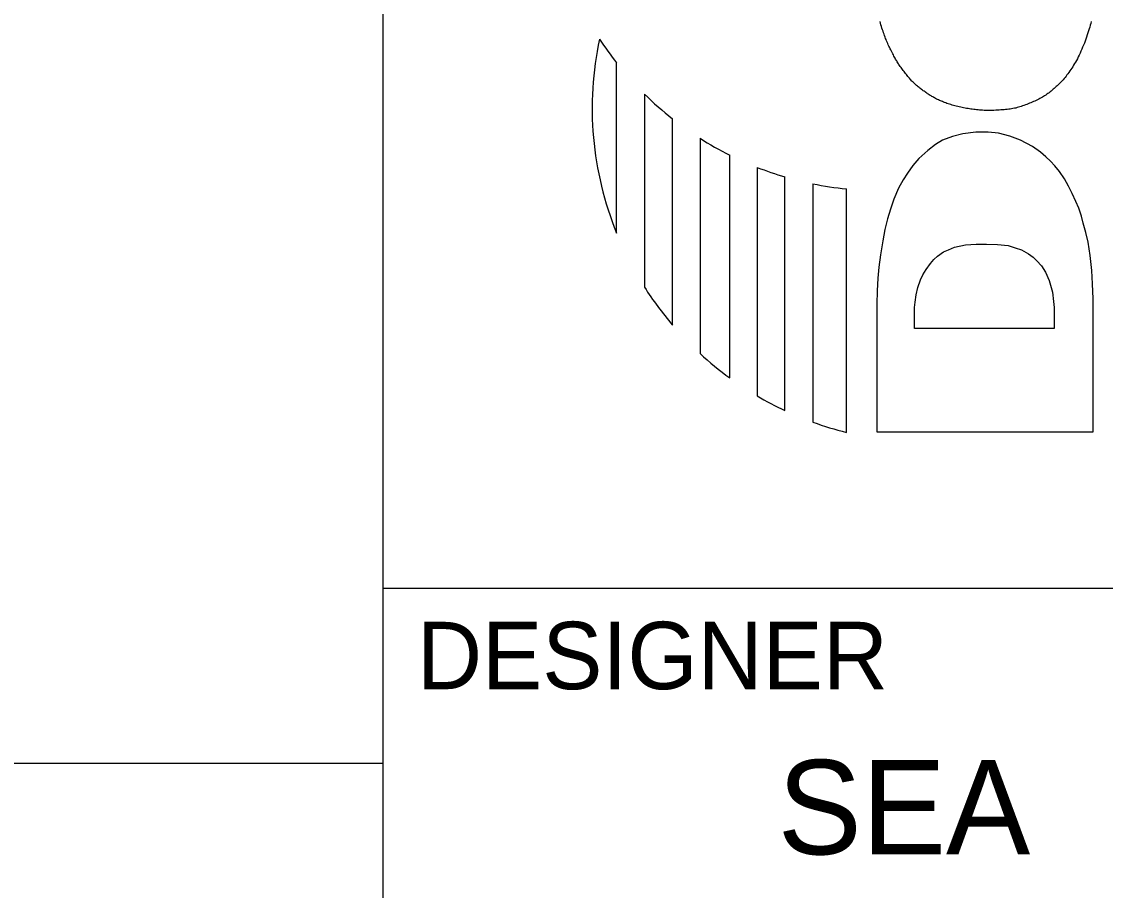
# Model space of a CAD drawing. Extents: x -1 to 34, y 0 to 22.
# Drawn here: x 31.464 to 33.071, y 2.552 to 3.841 of the extents above; entities that cross this region are included whole.
import ezdxf

# ---------------------------------------------------------------- set-up
doc = ezdxf.new("R2010")
doc.units = 0
for name, color, linetype in [('CM_Corridor_Final', 7, 'Continuous'), ('MD_P_GRADE_BREAK', 7, 'Continuous'), ('PF_X_Ground_Line', 7, 'Continuous')]:
    doc.layers.add(name, color=color, linetype=linetype)

msp = doc.modelspace()

# ---------------------------------------------------------------- linework, layer by layer
at = {"layer": 'CM_Corridor_Final'}
for p, q in [((32.7374, 3.8383), (32.7368, 3.8409)), ((32.7381, 3.8358), (32.7374, 3.8383)), ((32.7388, 3.8334), (32.7381, 3.8358)), ((32.7396, 3.831), (32.7388, 3.8334)), ((32.7403, 3.8286), (32.7396, 3.831)), ((32.7411, 3.8263), (32.7403, 3.8286)), ((32.7418, 3.8241), (32.7411, 3.8263)), ((33.046, 3.8269), (33.0451, 3.8239)), ((33.0469, 3.8298), (33.046, 3.8269)), ((33.0477, 3.8326), (33.0469, 3.8298)), ((33.0484, 3.8353), (33.0477, 3.8326)), ((33.0491, 3.838), (33.0484, 3.8353)), ((33.0498, 3.8406), (33.0491, 3.838)), ((32.7426, 3.8219), (32.7418, 3.8241)), ((32.7434, 3.8198), (32.7426, 3.8219)), ((32.7441, 3.8178), (32.7434, 3.8198)), ((32.7449, 3.8158), (32.7441, 3.8178)), ((32.7457, 3.8139), (32.7449, 3.8158)), ((32.7465, 3.812), (32.7457, 3.8139)), ((32.7473, 3.8101), (32.7465, 3.812)), ((32.7482, 3.8082), (32.7473, 3.8101)), ((33.0409, 3.8117), (33.0397, 3.8086)), ((33.042, 3.8148), (33.0409, 3.8117)), ((33.0431, 3.8178), (33.042, 3.8148)), ((33.0441, 3.8209), (33.0431, 3.8178)), ((33.0451, 3.8239), (33.0441, 3.8209)), ((32.749, 3.8063), (32.7482, 3.8082)), ((32.7499, 3.8044), (32.749, 3.8063)), ((32.7508, 3.8025), (32.7499, 3.8044)), ((32.7518, 3.8005), (32.7508, 3.8025)), ((32.7527, 3.7986), (32.7518, 3.8005)), ((32.7537, 3.7967), (32.7527, 3.7986)), ((32.7546, 3.7948), (32.7537, 3.7967)), ((32.7555, 3.7929), (32.7546, 3.7948)), ((32.7565, 3.7912), (32.7555, 3.7929)), ((33.0333, 3.7938), (33.032, 3.791)), ((33.0346, 3.7966), (33.0333, 3.7938)), ((33.036, 3.7996), (33.0346, 3.7966)), ((33.0372, 3.8026), (33.036, 3.7996)), ((33.0385, 3.8056), (33.0372, 3.8026)), ((33.0397, 3.8086), (33.0385, 3.8056)), ((32.7573, 3.7895), (32.7565, 3.7912)), ((32.7582, 3.7879), (32.7573, 3.7895)), ((32.759, 3.7864), (32.7582, 3.7879)), ((32.7598, 3.7849), (32.759, 3.7864)), ((32.7606, 3.7836), (32.7598, 3.7849)), ((32.7614, 3.7822), (32.7606, 3.7836)), ((32.7622, 3.7809), (32.7614, 3.7822)), ((32.7631, 3.7795), (32.7622, 3.7809)), ((32.7639, 3.7782), (32.7631, 3.7795)), ((32.7648, 3.7768), (32.7639, 3.7782)), ((32.7658, 3.7754), (32.7648, 3.7768)), ((33.0252, 3.7783), (33.0238, 3.776)), ((33.0265, 3.7806), (33.0252, 3.7783)), ((33.0279, 3.7831), (33.0265, 3.7806)), ((33.0293, 3.7856), (33.0279, 3.7831)), ((33.0306, 3.7882), (33.0293, 3.7856)), ((33.032, 3.791), (33.0306, 3.7882)), ((32.7668, 3.774), (32.7658, 3.7754)), ((32.7678, 3.7726), (32.7668, 3.774)), ((32.7689, 3.7711), (32.7678, 3.7726)), ((32.77, 3.7696), (32.7689, 3.7711)), ((32.7711, 3.7681), (32.77, 3.7696)), ((32.7723, 3.7666), (32.7711, 3.7681)), ((32.7734, 3.7651), (32.7723, 3.7666)), ((32.7746, 3.7636), (32.7734, 3.7651)), ((32.7758, 3.7621), (32.7746, 3.7636)), ((32.777, 3.7607), (32.7758, 3.7621)), ((32.7781, 3.7593), (32.777, 3.7607)), ((33.0139, 3.7615), (33.0125, 3.7596)), ((33.0154, 3.7634), (33.0139, 3.7615)), ((33.0168, 3.7653), (33.0154, 3.7634)), ((33.0182, 3.7674), (33.0168, 3.7653)), ((33.0196, 3.7694), (33.0182, 3.7674)), ((33.021, 3.7716), (33.0196, 3.7694)), ((33.0224, 3.7737), (33.021, 3.7716)), ((33.0238, 3.776), (33.0224, 3.7737)), ((32.7793, 3.7579), (32.7781, 3.7593)), ((32.7804, 3.7566), (32.7793, 3.7579)), ((32.7815, 3.7553), (32.7804, 3.7566)), ((32.7826, 3.7542), (32.7815, 3.7553)), ((32.7836, 3.753), (32.7826, 3.7542)), ((32.7846, 3.752), (32.7836, 3.753)), ((32.7857, 3.751), (32.7846, 3.752)), ((32.7867, 3.75), (32.7857, 3.751)), ((32.7877, 3.749), (32.7867, 3.75)), ((32.7888, 3.748), (32.7877, 3.749)), ((32.7899, 3.747), (32.7888, 3.748)), ((32.791, 3.746), (32.7899, 3.747)), ((32.7921, 3.745), (32.791, 3.746)), ((32.7933, 3.744), (32.7921, 3.745)), ((32.9995, 3.7455), (32.9981, 3.7442)), ((33.001, 3.7469), (32.9995, 3.7455)), ((33.0024, 3.7483), (33.001, 3.7469)), ((33.0039, 3.7498), (33.0024, 3.7483)), ((33.0053, 3.7513), (33.0039, 3.7498)), ((33.0067, 3.7528), (33.0053, 3.7513)), ((33.0082, 3.7544), (33.0067, 3.7528)), ((33.0096, 3.7561), (33.0082, 3.7544)), ((33.0111, 3.7578), (33.0096, 3.7561)), ((33.0125, 3.7596), (33.0111, 3.7578)), ((32.7946, 3.743), (32.7933, 3.744)), ((32.7958, 3.742), (32.7946, 3.743)), ((32.7971, 3.741), (32.7958, 3.742)), ((32.7983, 3.74), (32.7971, 3.741)), ((32.7996, 3.739), (32.7983, 3.74)), ((32.8009, 3.7381), (32.7996, 3.739)), ((32.8021, 3.7372), (32.8009, 3.7381)), ((32.8034, 3.7363), (32.8021, 3.7372)), ((32.8047, 3.7354), (32.8034, 3.7363)), ((32.8059, 3.7345), (32.8047, 3.7354)), ((32.8072, 3.7337), (32.8059, 3.7345)), ((32.8085, 3.7328), (32.8072, 3.7337)), ((32.8098, 3.732), (32.8085, 3.7328)), ((32.8111, 3.7312), (32.8098, 3.732)), ((32.8124, 3.7304), (32.8111, 3.7312)), ((32.8137, 3.7296), (32.8124, 3.7304)), ((32.815, 3.7288), (32.8137, 3.7296)), ((32.8163, 3.728), (32.815, 3.7288)), ((32.9774, 3.7285), (32.9757, 3.7275)), ((32.9791, 3.7295), (32.9774, 3.7285)), ((32.9808, 3.7306), (32.9791, 3.7295)), ((32.9824, 3.7317), (32.9808, 3.7306)), ((32.9841, 3.7328), (32.9824, 3.7317)), ((32.9857, 3.7339), (32.9841, 3.7328)), ((32.9873, 3.7351), (32.9857, 3.7339)), ((32.9889, 3.7363), (32.9873, 3.7351)), ((32.9905, 3.7376), (32.9889, 3.7363)), ((32.992, 3.7389), (32.9905, 3.7376)), ((32.9936, 3.7402), (32.992, 3.7389)), ((32.9951, 3.7415), (32.9936, 3.7402)), ((32.9966, 3.7428), (32.9951, 3.7415)), ((32.9981, 3.7442), (32.9966, 3.7428)), ((32.8177, 3.7273), (32.8163, 3.728)), ((32.8191, 3.7265), (32.8177, 3.7273)), ((32.8204, 3.7258), (32.8191, 3.7265)), ((32.8218, 3.7251), (32.8204, 3.7258)), ((32.8233, 3.7244), (32.8218, 3.7251)), ((32.8247, 3.7238), (32.8233, 3.7244)), ((32.8262, 3.7231), (32.8247, 3.7238)), ((32.8277, 3.7225), (32.8262, 3.7231)), ((32.8293, 3.7219), (32.8277, 3.7225)), ((32.8309, 3.7212), (32.8293, 3.7219)), ((32.8325, 3.7206), (32.8309, 3.7212)), ((32.8342, 3.72), (32.8325, 3.7206)), ((32.836, 3.7193), (32.8342, 3.72)), ((32.8378, 3.7187), (32.836, 3.7193)), ((32.8397, 3.7181), (32.8378, 3.7187)), ((32.8416, 3.7175), (32.8397, 3.7181)), ((32.8436, 3.7168), (32.8416, 3.7175)), ((32.8456, 3.7163), (32.8436, 3.7168)), ((32.8477, 3.7157), (32.8456, 3.7163)), ((32.8498, 3.7151), (32.8477, 3.7157)), ((32.8519, 3.7146), (32.8498, 3.7151)), ((32.8541, 3.7141), (32.8519, 3.7146)), ((32.8563, 3.7136), (32.8541, 3.7141)), ((32.8585, 3.7131), (32.8563, 3.7136)), ((32.8607, 3.7127), (32.8585, 3.7131)), ((32.8629, 3.7123), (32.8607, 3.7127)), ((32.865, 3.7119), (32.8629, 3.7123)), ((32.9379, 3.7124), (32.9359, 3.712)), ((32.9399, 3.713), (32.9379, 3.7124)), ((32.942, 3.7135), (32.9399, 3.713)), ((32.944, 3.7142), (32.942, 3.7135)), ((32.9461, 3.7148), (32.944, 3.7142)), ((32.9481, 3.7155), (32.9461, 3.7148)), ((32.9501, 3.7162), (32.9481, 3.7155)), ((32.9522, 3.717), (32.9501, 3.7162)), ((32.9542, 3.7178), (32.9522, 3.717)), ((32.9563, 3.7186), (32.9542, 3.7178)), ((32.9583, 3.7194), (32.9563, 3.7186)), ((32.9604, 3.7202), (32.9583, 3.7194)), ((32.9624, 3.7211), (32.9604, 3.7202)), ((32.9644, 3.722), (32.9624, 3.7211)), ((32.9664, 3.7228), (32.9644, 3.722)), ((32.9683, 3.7237), (32.9664, 3.7228)), ((32.9702, 3.7247), (32.9683, 3.7237)), ((32.9721, 3.7256), (32.9702, 3.7247)), ((32.9739, 3.7265), (32.9721, 3.7256)), ((32.9757, 3.7275), (32.9739, 3.7265)), ((32.8672, 3.7115), (32.865, 3.7119)), ((32.8693, 3.7111), (32.8672, 3.7115)), ((32.8714, 3.7108), (32.8693, 3.7111)), ((32.8735, 3.7105), (32.8714, 3.7108)), ((32.8756, 3.7102), (32.8735, 3.7105)), ((32.8777, 3.71), (32.8756, 3.7102)), ((32.8798, 3.7097), (32.8777, 3.71)), ((32.882, 3.7095), (32.8798, 3.7097)), ((32.8841, 3.7093), (32.882, 3.7095)), ((32.8864, 3.7092), (32.8841, 3.7093)), ((32.8886, 3.709), (32.8864, 3.7092)), ((32.891, 3.7089), (32.8886, 3.709)), ((32.8933, 3.7088), (32.891, 3.7089)), ((32.8957, 3.7088), (32.8933, 3.7088)), ((32.8981, 3.7088), (32.8957, 3.7088)), ((32.9006, 3.7088), (32.8981, 3.7088)), ((32.9031, 3.7089), (32.9006, 3.7088)), ((32.9057, 3.7089), (32.9031, 3.7089)), ((32.9082, 3.709), (32.9057, 3.7089)), ((32.9108, 3.7092), (32.9082, 3.709)), ((32.9134, 3.7093), (32.9108, 3.7092)), ((32.9159, 3.7095), (32.9134, 3.7093)), ((32.9183, 3.7097), (32.9159, 3.7095)), ((32.9207, 3.7099), (32.9183, 3.7097)), ((32.923, 3.7101), (32.9207, 3.7099)), ((32.9253, 3.7103), (32.923, 3.7101)), ((32.9275, 3.7106), (32.9253, 3.7103)), ((32.9296, 3.7109), (32.9275, 3.7106)), ((32.9317, 3.7112), (32.9296, 3.7109)), ((32.9338, 3.7116), (32.9317, 3.7112)), ((32.9359, 3.712), (32.9338, 3.7116)), ((32.8295, 3.6645), (32.8191, 3.6583)), ((32.8444, 3.6703), (32.8295, 3.6645)), ((32.8597, 3.6743), (32.8444, 3.6703)), ((32.8786, 3.6766), (32.8597, 3.6743)), ((32.8969, 3.6764), (32.8786, 3.6766)), ((32.9123, 3.6751), (32.8969, 3.6764)), ((32.929, 3.6707), (32.9123, 3.6751)), ((32.945, 3.6648), (32.929, 3.6707)), ((32.9626, 3.6555), (32.945, 3.6648)), ((32.8074, 3.6496), (32.7943, 3.6374)), ((32.8191, 3.6583), (32.8074, 3.6496)), ((32.9748, 3.647), (32.9626, 3.6555)), ((32.7943, 3.6374), (32.7851, 3.627)), ((32.9827, 3.6402), (32.9748, 3.647)), ((32.9895, 3.6335), (32.9827, 3.6402)), ((32.9961, 3.6264), (32.9895, 3.6335)), ((32.7851, 3.627), (32.7774, 3.6158)), ((33.0029, 3.618), (32.9961, 3.6264)), ((33.0104, 3.6072), (33.0029, 3.618)), ((32.771, 3.6059), (32.7642, 3.5934)), ((32.7774, 3.6158), (32.771, 3.6059)), ((33.0164, 3.5965), (33.0104, 3.6072)), ((32.7642, 3.5934), (32.7572, 3.5773)), ((33.0218, 3.5858), (33.0164, 3.5965)), ((33.0271, 3.5738), (33.0218, 3.5858)), ((32.7572, 3.5773), (32.752, 3.5625)), ((33.0313, 3.5639), (33.0271, 3.5738)), ((32.752, 3.5625), (32.7477, 3.5478)), ((33.0354, 3.5519), (33.0313, 3.5639)), ((33.0381, 3.5414), (33.0354, 3.5519)), ((32.7477, 3.5478), (32.7439, 3.5324)), ((33.0419, 3.5279), (33.0381, 3.5414)), ((32.7439, 3.5324), (32.7409, 3.5152)), ((33.0452, 3.5133), (33.0419, 3.5279)), ((32.7409, 3.5152), (32.7374, 3.4947)), ((32.8384, 3.5022), (32.8473, 3.5061)), ((32.8473, 3.5061), (32.8636, 3.5096)), ((32.8636, 3.5096), (32.8794, 3.5102)), ((32.8794, 3.5102), (32.8947, 3.5103)), ((32.8947, 3.5103), (32.9109, 3.51)), ((32.9109, 3.51), (32.9265, 3.5082)), ((32.9265, 3.5082), (32.9373, 3.5051)), ((32.9373, 3.5051), (32.9466, 3.502)), ((33.0484, 3.4936), (33.0452, 3.5133)), ((32.7374, 3.4947), (32.7351, 3.4765)), ((32.8113, 3.4817), (32.8167, 3.4878)), ((32.8167, 3.4878), (32.8219, 3.4928)), ((32.8219, 3.4928), (32.831, 3.4988)), ((32.831, 3.4988), (32.8384, 3.5022)), ((32.9466, 3.502), (32.9567, 3.4961)), ((32.9567, 3.4961), (32.9636, 3.4909)), ((32.9636, 3.4909), (32.9693, 3.4856)), ((33.0509, 3.4711), (33.0484, 3.4936)), ((32.7351, 3.4765), (32.7336, 3.4599)), ((32.8002, 3.4649), (32.805, 3.4727)), ((32.805, 3.4727), (32.8113, 3.4817)), ((32.9693, 3.4856), (32.976, 3.4783)), ((32.976, 3.4783), (32.9822, 3.4688)), ((32.7336, 3.4599), (32.7325, 3.4409)), ((32.7929, 3.4461), (32.7966, 3.4575)), ((32.7966, 3.4575), (32.8002, 3.4649)), ((32.9822, 3.4688), (32.9875, 3.4567)), ((32.9875, 3.4567), (32.9923, 3.4392)), ((33.0519, 3.4515), (33.0509, 3.4711)), ((32.7325, 3.4409), (32.7318, 3.4215)), ((32.7901, 3.435), (32.7929, 3.4461)), ((32.9923, 3.4392), (32.9941, 3.4255)), ((33.0528, 3.4295), (33.0519, 3.4515)), ((32.7879, 3.4166), (32.7886, 3.4242)), ((32.7886, 3.4242), (32.7901, 3.435)), ((32.9941, 3.4255), (32.9947, 3.4166)), ((33.0528, 3.2321), (33.0528, 3.4295)), ((32.7318, 3.4215), (32.7318, 3.2321)), ((32.7879, 3.3854), (32.7879, 3.4166)), ((32.9947, 3.4166), (32.9947, 3.3854)), ((32.9947, 3.3854), (32.7879, 3.3854)), ((32.7318, 3.2321), (33.0528, 3.2321))]:
    msp.add_line(p, q, dxfattribs=at)
for points in [[(32.3461, 3.5269), (32.3461, 3.7793)], [(32.3874, 3.7332), (32.3874, 3.4468)], [(32.429, 3.3904), (32.429, 3.6964)], [(32.4698, 3.6675), (32.4698, 3.3481)], [(32.5138, 3.3119), (32.5138, 3.6426)], [(32.5545, 3.6244), (32.5545, 3.2852)], [(32.5957, 3.2634), (32.5957, 3.6103)], [(32.6371, 3.6), (32.6371, 3.2463)], [(32.687, 3.2311), (32.687, 3.5925)]]:
    msp.add_lwpolyline(points, dxfattribs=at)
for centre, radius, start, end in [((32.7985, 3.7116), 0.4887, 167.8403, 202.2153), ((32.7359, 4.086), 0.496, 213.1881, 218.2009), ((32.7359, 4.086), 0.496, 225.3506, 231.7757), ((32.7359, 4.086), 0.496, 237.5471, 243.3934), ((32.7359, 4.086), 0.496, 248.5465, 253.5848), ((32.7359, 4.086), 0.496, 258.5092, 264.339), ((32.8064, 3.713), 0.4965, 212.4278, 220.5248), ((32.8064, 3.713), 0.4965, 227.3071, 233.8848), ((32.8064, 3.713), 0.4965, 239.5109, 244.8932), ((32.8064, 3.713), 0.4965, 250.062, 256.0821)]:
    msp.add_arc(centre, radius, start, end, dxfattribs=at)
at = {"layer": 'MD_P_GRADE_BREAK'}
msp.add_line((25.1966, 2.74), (32, 2.74), dxfattribs=at)
at = {"layer": 'PF_X_Ground_Line'}
for p, q in [((32, 0.5), (32, 21.5)), ((32, 3), (33.5, 3))]:
    msp.add_line(p, q, dxfattribs=at)

# ---------------------------------------------------------------- texts
at = {"layer": 'CM_Corridor_Final'}
for s, height, p in [('DESIGNER', 0.1, (32.05, 2.85)), ('SEA', 0.14, (32.5848, 2.605))]:
    msp.add_text(s, height=height, dxfattribs=at).set_placement(p)

doc.saveas('drawing.dxf')
